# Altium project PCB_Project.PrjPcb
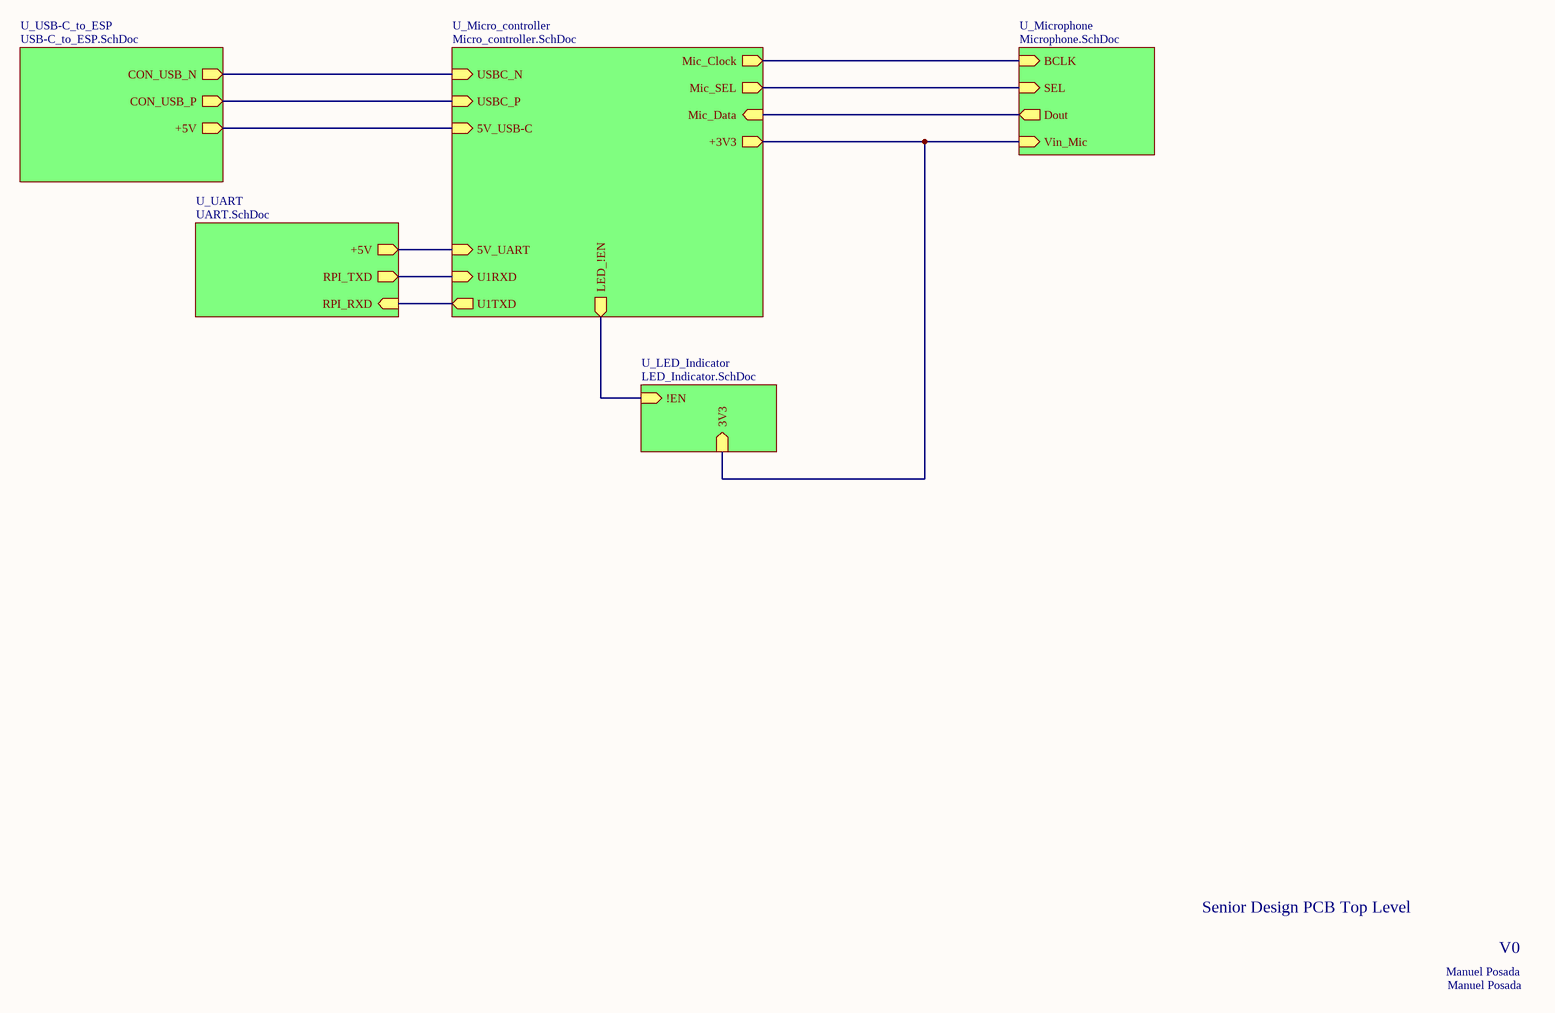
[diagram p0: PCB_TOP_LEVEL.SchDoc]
6 sheets, 63 parts. Net scope: hierarchical (ports join the sheet entries above them; power ports are global).
Board file: PCB1.PcbDoc
Sheets:
  PCB_TOP_LEVEL.SchDoc
    U_Micro_controller = Micro_controller.SchDoc
    U_USB-C_to_ESP = USB-C_to_ESP.SchDoc
    U_Microphone = Microphone.SchDoc
    U_UART = UART.SchDoc
    U_LED_Indicator = LED_Indicator.SchDoc

## Sheet PCB_TOP_LEVEL.SchDoc
size B; SheetNumber: 1; SheetTotal: 6

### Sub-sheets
U_LED_Indicator = LED_Indicator.SchDoc: 3V3 (in), !EN (in)
U_Micro_controller = Micro_controller.SchDoc: Mic_Data (in), Mic_SEL (out), Mic_Clock (out), U1TXD (out), U1RXD (in), LED_!EN (out), USBC_N (in), USBC_P (in), 5V_USB-C (in), 5V_UART (in), +3V3 (out)
U_Microphone = Microphone.SchDoc: Vin_Mic (in), BCLK (in), Dout (out), SEL (in)
U_UART = UART.SchDoc: RPI_RXD (in), RPI_TXD (out), +5V (out)
U_USB-C_to_ESP = USB-C_to_ESP.SchDoc: +5V (out), CON_USB_N (out), CON_USB_P (out)

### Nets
3.3V: sheet U_Micro_controller/+3V3, sheet U_Microphone/Vin_Mic, sheet U_LED_Indicator/3V3
GPIO6: sheet U_Micro_controller/Mic_SEL, sheet U_Microphone/SEL
GPIO7: sheet U_Micro_controller/Mic_Data, sheet U_Microphone/Dout
GPIO8: sheet U_Micro_controller/Mic_Clock, sheet U_Microphone/BCLK
GPIO17: sheet U_Micro_controller/U1TXD, sheet U_UART/RPI_RXD
GPIO18: sheet U_Micro_controller/U1RXD, sheet U_UART/RPI_TXD
GPIO19: sheet U_Micro_controller/USBC_N, sheet U_USB-C_to_ESP/CON_USB_N
GPIO20: sheet U_Micro_controller/USBC_P, sheet U_USB-C_to_ESP/CON_USB_P
GPIO38: sheet U_Micro_controller/LED_!EN, sheet U_LED_Indicator/!EN
NetR1_1: sheet U_Micro_controller/5V_USB-C, sheet U_USB-C_to_ESP/+5V
NetR4_1: sheet U_Micro_controller/5V_UART, sheet U_UART/+5V

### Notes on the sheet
- Senior Design PCB Top Level
- Manuel Posada
- V0

## Sheet Micro_controller.SchDoc
size C; SheetNumber: 3; SheetTotal: 6
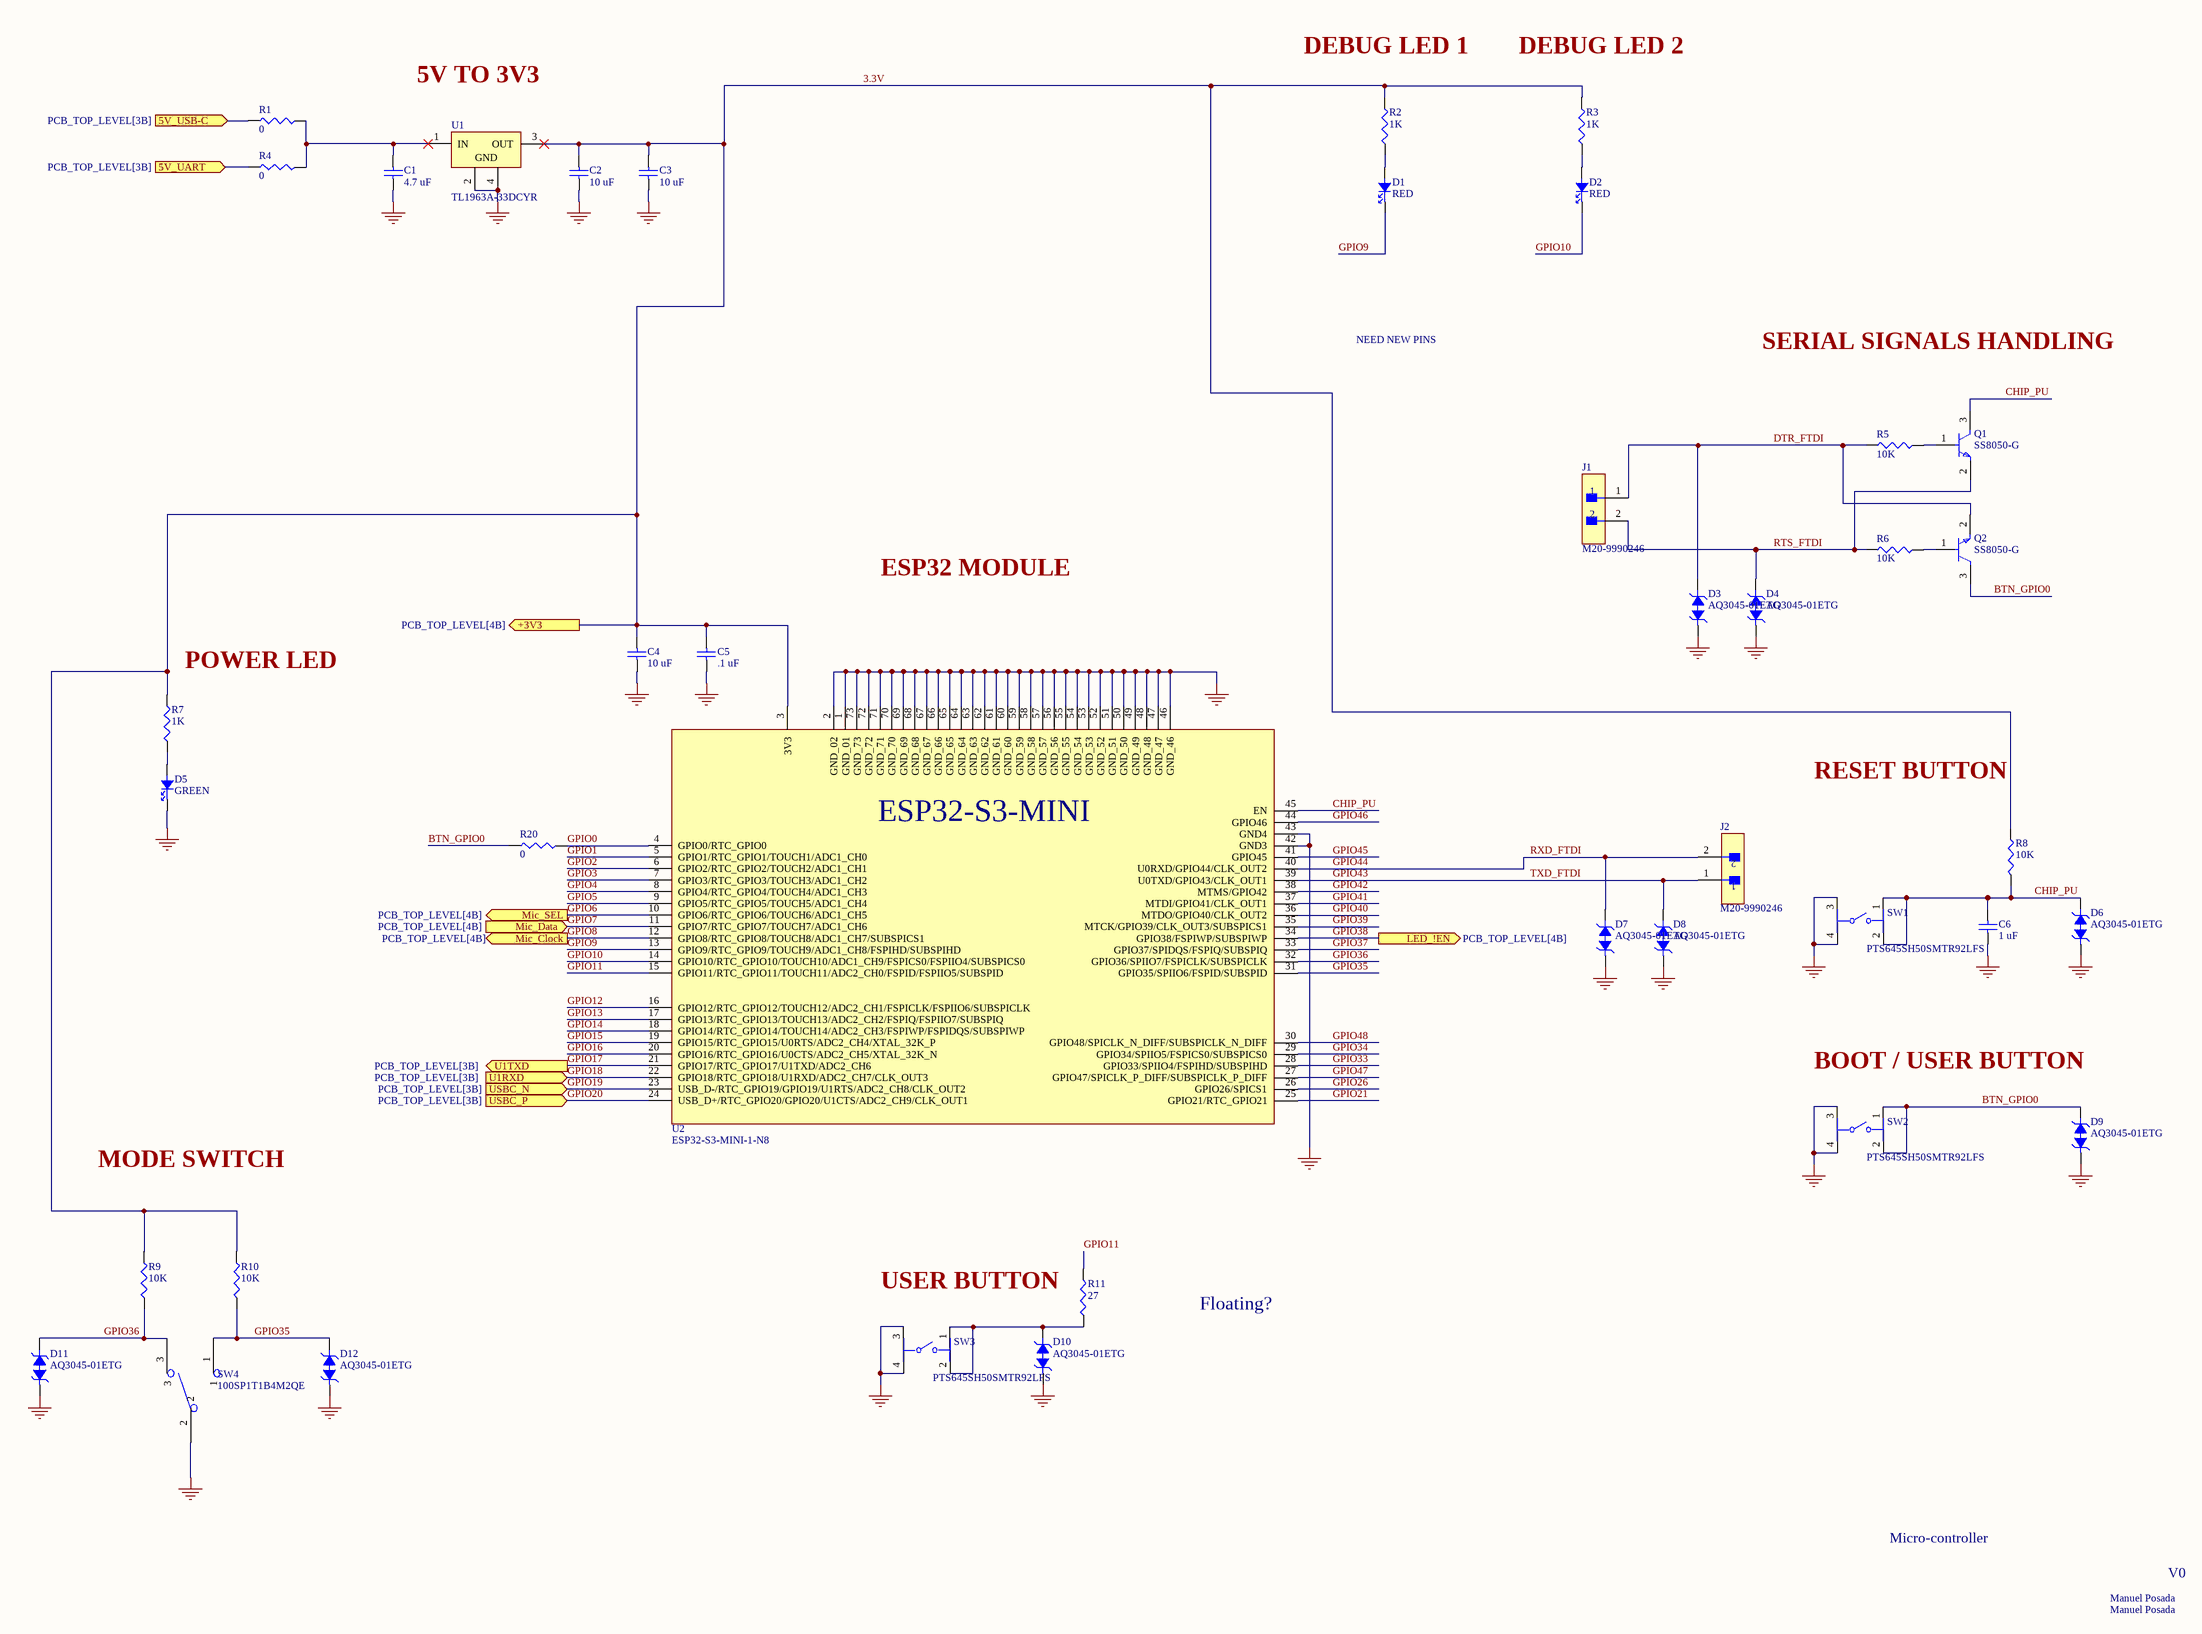
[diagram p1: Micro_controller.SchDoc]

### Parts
C1  4.7 uF  [CAP_CL21_SAM-L]
C2  10 uF  [CAP_CL21_SAM-L]
C3  10 uF  [CAP_CL21_SAM-L]
C4  10 uF  [CAP_CL21_SAM-L]
C5  .1 uF  [CAP_CL21_SAM-L]
C6  1 uF  [CAP_CL21_SAM-L]
D1  RED  [LED0402R]
D2  RED  [LED0402R]
D3  AQ3045-01ETG  [SOD882]
D4  AQ3045-01ETG  [SOD882]
D5  GREEN  [LED0402G]
D6  AQ3045-01ETG  [SOD882]
D7  AQ3045-01ETG  [SOD882]
D8  AQ3045-01ETG  [SOD882]
D9  AQ3045-01ETG  [SOD882]
D10  AQ3045-01ETG  [SOD882]
D11  AQ3045-01ETG  [SOD882]
D12  AQ3045-01ETG  [SOD882]
J1  M20-9990246  [CONN2_M20-999_1x2_HRW]
J2  M20-9990246  [CONN2_M20-999_1x2_HRW]
Q1  SS8050-G  [FP-SS8050-G-IPC_B]
Q2  SS8050-G  [FP-SS8050-G-IPC_B]
R1  0  [RES_1220_SUS-L]
R2  1K  [RES_1220_SUS-L]
R3  1K  [RES_1220_SUS-L]
R4  0  [RES_1220_SUS-L]
R5  10K  [RES_1220_SUS-L]
R6  10K  [RES_1220_SUS-L]
R7  1K  [RES_1220_SUS-L]
R8  10K  [RES_1220_SUS-L]
R9  10K  [RES_1220_SUS-L]
R10  10K  [RES_1220_SUS-L]
R11  27  [RES_1220_SUS-L]
R20  0  [RES_1220_SUS-L]
SW1  PTS645SH50SMTR92LFS  [FP-PTS645SH50SMTR92LFS-MFG]
SW2  PTS645SH50SMTR92LFS  [FP-PTS645SH50SMTR92LFS-MFG]
SW3  PTS645SH50SMTR92LFS  [FP-PTS645SH50SMTR92LFS-MFG]
SW4  100SP1T1B4M2QE  [100SP1T1_EWI]
U1  TL1963A-33DCYR  [DCY0004A_N]
U2  ESP32-S3-MINI-1-N8  [XCVR_ESP32-S3-MINI-1-N8]

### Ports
5V_UART (in, see PCB_TOP_LEVEL[3B]), 5V_USB-C (in, see PCB_TOP_LEVEL[3B]), +3V3 (out, see PCB_TOP_LEVEL[4B]), LED_!EN (out, see PCB_TOP_LEVEL[4B]), Mic_Clock (out, see PCB_TOP_LEVEL[4B]), Mic_Data (in, see PCB_TOP_LEVEL[4B]), Mic_SEL (out, see PCB_TOP_LEVEL[4B]), U1RXD (in, see PCB_TOP_LEVEL[3B]), U1TXD (out, see PCB_TOP_LEVEL[3B]), USBC_N (in, see PCB_TOP_LEVEL[3B]), USBC_P (in, see PCB_TOP_LEVEL[3B])

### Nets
GND: C1.1 C2.1 C3.1 C4.1 C5.1 C6.1 D3.1 D4.1 D5.1 D6.1 D7.1 D8.1 D9.1 D10.1 D11.1 D12.1 SW1.3 SW1.4 SW2.3 SW2.4 SW3.3 SW3.4 SW4.2 U1.2(GND) U1.4(GND) U2.1(GND_01) U2.2(GND_02) U2.42(GND3) U2.43(GND4) U2.46(GND_46) U2.47(GND_47) U2.48(GND_48) U2.49(GND_49) U2.50(GND_50) U2.51(GND_51) U2.52(GND_52) U2.53(GND_53) U2.54(GND_54) U2.55(GND_55) U2.56(GND_56) U2.57(GND_57) U2.58(GND_58) U2.59(GND_59) U2.60(GND_60) U2.61(GND_61) U2.62(GND_62) U2.63(GND_63) U2.64(GND_64) U2.65(GND_65) U2.66(GND_66) U2.67(GND_67) U2.68(GND_68) U2.69(GND_69) U2.70(GND_70) U2.71(GND_71) U2.72(GND_72) U2.73(GND_73)
3.3V: C2.2 C3.2 C4.2 C5.2 R2.2 R3.2 R7.2 R8.2 R9.2 R10.2 U1.3(OUT) U2.3(3V3) ; port +3V3
BTN_GPIO0: D9.2 Q2.3(C) R20.1 SW2.1 SW2.2
CHIP_PU: C6.2 D6.2 Q1.3(C) R8.1 SW1.1 SW1.2 U2.45(EN)
DTR_FTDI: D3.2 J1.1 Q2.2(E) R5.1
GPIO0: R20.2 U2.4(GPIO0/RTC_GPIO0)
GPIO1: U2.5(GPIO1/RTC_GPIO1/TOUCH1/ADC1_CH0)
GPIO2: U2.6(GPIO2/RTC_GPIO2/TOUCH2/ADC1_CH1)
GPIO3: U2.7(GPIO3/RTC_GPIO3/TOUCH3/ADC1_CH2)
GPIO4: U2.8(GPIO4/RTC_GPIO4/TOUCH4/ADC1_CH3)
GPIO5: U2.9(GPIO5/RTC_GPIO5/TOUCH5/ADC1_CH4)
GPIO6: U2.10(GPIO6/RTC_GPIO6/TOUCH6/ADC1_CH5) ; port Mic_SEL
GPIO7: U2.11(GPIO7/RTC_GPIO7/TOUCH7/ADC1_CH6) ; port Mic_Data
GPIO8: U2.12(GPIO8/RTC_GPIO8/TOUCH8/ADC1_CH7/SUBSPICS1) ; port Mic_Clock
GPIO9: D1.1 U2.13(GPIO9/RTC_GPIO9/TOUCH9/ADC1_CH8/FSPIHD/SUBSPIHD)
GPIO10: D2.1 U2.14(GPIO10/RTC_GPIO10/TOUCH10/ADC1_CH9/FSPICS0/FSPIIO4/SUBSPICS0)
GPIO11: R11.2 U2.15(GPIO11/RTC_GPIO11/TOUCH11/ADC2_CH0/FSPID/FSPIIO5/SUBSPID)
GPIO12: U2.16(GPIO12/RTC_GPIO12/TOUCH12/ADC2_CH1/FSPICLK/FSPIIO6/SUBSPICLK)
GPIO13: U2.17(GPIO13/RTC_GPIO13/TOUCH13/ADC2_CH2/FSPIQ/FSPIIO7/SUBSPIQ)
GPIO14: U2.18(GPIO14/RTC_GPIO14/TOUCH14/ADC2_CH3/FSPIWP/FSPIDQS/SUBSPIWP)
GPIO15: U2.19(GPIO15/RTC_GPIO15/U0RTS/ADC2_CH4/XTAL_32K_P)
GPIO16: U2.20(GPIO16/RTC_GPIO16/U0CTS/ADC2_CH5/XTAL_32K_N)
GPIO17: U2.21(GPIO17/RTC_GPIO17/U1TXD/ADC2_CH6) ; port U1TXD
GPIO18: U2.22(GPIO18/RTC_GPIO18/U1RXD/ADC2_CH7/CLK_OUT3) ; port U1RXD
GPIO19: U2.23(USB_D-/RTC_GPIO19/GPIO19/U1RTS/ADC2_CH8/CLK_OUT2) ; port USBC_N
GPIO20: U2.24(USB_D+/RTC_GPIO20/GPIO20/U1CTS/ADC2_CH9/CLK_OUT1) ; port USBC_P
GPIO21: U2.25(GPIO21/RTC_GPIO21)
GPIO26: U2.26(GPIO26/SPICS1)
GPIO33: U2.28(GPIO33/SPIIO4/FSPIHD/SUBSPIHD)
GPIO34: U2.29(GPIO34/SPIIO5/FSPICS0/SUBSPICS0)
GPIO35: D12.2 R10.1 SW4.1 U2.31(GPIO35/SPIIO6/FSPID/SUBSPID)
GPIO36: D11.2 R9.1 SW4.3 U2.32(GPIO36/SPIIO7/FSPICLK/SUBSPICLK)
GPIO37: U2.33(GPIO37/SPIDQS/FSPIQ/SUBSPIQ)
GPIO38: U2.34(GPIO38/FSPIWP/SUBSPIWP) ; port LED_!EN
GPIO39: U2.35(MTCK/GPIO39/CLK_OUT3/SUBSPICS1)
GPIO40: U2.36(MTDO/GPIO40/CLK_OUT2)
GPIO41: U2.37(MTDI/GPIO41/CLK_OUT1)
GPIO42: U2.38(MTMS/GPIO42)
GPIO43: D8.2 J2.1 U2.39(U0TXD/GPIO43/CLK_OUT1)  [also labelled TXD_FTDI]
GPIO44: D7.2 J2.2 U2.40(U0RXD/GPIO44/CLK_OUT2)  [also labelled RXD_FTDI]
GPIO45: U2.41(GPIO45)
GPIO46: U2.44(GPIO46)
GPIO47: U2.27(GPIO47/SPICLK_P_DIFF/SUBSPICLK_P_DIFF)
GPIO48: U2.30(GPIO48/SPICLK_N_DIFF/SUBSPICLK_N_DIFF)
RTS_FTDI: D4.2 J1.2 Q1.2(E) R6.1
NetC1_2: C1.2 R1.2 R4.2 U1.1(IN)
NetD1_2: D1.2 R2.1
NetD2_2: D2.2 R3.1
NetD5_2: D5.2 R7.1
NetD10_2: D10.2 R11.1 SW3.1 SW3.2
NetQ1_1: Q1.1(B) R5.2
NetQ2_1: Q2.1(B) R6.2
NetR1_1: R1.1 ; port 5V_USB-C
NetR4_1: R4.1 ; port 5V_UART

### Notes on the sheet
- DEBUG LED 1
- DEBUG LED 2
- 5V TO 3V3
- SERIAL SIGNALS HANDLING
- NEED NEW PINS
- ESP32 MODULE
- (near R7) POWER LED
- RESET BUTTON
- BOOT / USER BUTTON
- MODE SWITCH
- USER BUTTON
- Floating?
- Micro-controller
- Manuel Posada
- V0

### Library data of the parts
C1 = CL21A475KAQNNNE: 25V 4.7uF X5R ±10% 0805 Multilayer Ceramic Capacitors MLCC - SMD/SMT ROHS; Manufacturer: Samsung Electro-Mechanics; Value: 4.7µF
C2-C4 = CL21B106KOQNNNE: 16V 10uF X7R ±10% 0805 Multilayer Ceramic Capacitors MLCC - SMD/SMT ROHS; Manufacturer: Samsung Electro-Mechanics; Value: 10µF
C5 = CL21B104KBCNNNC: 50V 100nF X7R ±10% 0805 Multilayer Ceramic Capacitors MLCC - SMD/SMT ROHS; Manufacturer: Samsung Electro-Mechanics
C6 = CL21B105KBFNNNE: 50V 1uF X7R ±10% 0805 Multilayer Ceramic Capacitors MLCC - SMD/SMT ROHS; Manufacturer: Samsung Electro-Mechanics; Value: 1µF
D1 D2 = VLMS1500-GS08: LED RED 0402 SMD; Manufacturer: Vishay; Shape: Rectangular; Forward Current: 30mA; Forward Voltage: 2.4V; Luminous Intensity-Nom: 54mcd; Channels: 1; Optoelectronic Device Type: SINGLE COLOR LED; Reverse Voltage-Max: 5V; Viewing Angle: 130°; Overall Height: 0.35mm
D3 D4 D6-D12 = AQ3045-01ETG: TVS DIODE 5.3VWM 12VC SOD882; Manufacturer: Littelfuse; Diode Element Material: SILICON; Package Body Material: Plastic; Polarity: Bidirectional; Max Breakdown Voltage: 9V; Min Breakdown Voltage: 6.8V; Diode Type: TRANS VOLTAGE SUPPRESSOR; Non-rep Peak Rev Power Dis-Max: 40W; Number of Elements: 1; Rep Pk Reverse Voltage-Max: 5.3V; Reference Standard: AEC-Q101
D5 = VLMG1500-GS08: LED YLW-GRN 0402 SMD; Manufacturer: Vishay; Color: Green,Yellow; Lens Color: Clear; Viewing Angle: 130°; Forward Current: 30mA; Forward Voltage: 2V; Luminous Intensity: 35mcd; Dominant Wavelength: 571nm; Test Current: 20mA; Number of Elements: 1; Power Dissipation: 75mW; Lens Style: Rectangular; Reverse Voltage: 5V
J1 J2 = M20-9990246: Connector Header Through Hole 2 position 0.100" (2.54mm); Manufacturer: Harwin; Connector Type: Male Pin; Contact Resistance: 30mΩ; Current Rating: 3A; Dielectric Material: Polyamide; Gender: Male; Insulation Resistance: 1GΩ; Number of Contacts: 2; Voltage Rating (AC): 750V
Q1 Q2 = SS8050-G: TRANS NPN 25V 1.5A SOT23-3; Manufacturer: Comchip
R1 R4 R20 = RC0805JR-070RL: GENERAL PURPOSE CHIP RESISTOR Metal Glaze/thick Film, 0.125W, 0ohm, Surface Mount, 0805; Manufacturer: Yageo Group; Power Dissipation: 125mW; Value: 0Ω; Temperature Coefficient: 300ppm/°C; Tolerance: 5%; Voltage Rating: 150V
R2 R3 R7 = RG2012P-102-B-T5: Res Thin Film 0805 1K Ohm 0.1% 0.125W(1/8W) ±25ppm/C Sulfur Resistant Pad SMD Automotive T/R; Manufacturer: Susumu; Max Power Dissipation: 125mW; Value: 1kΩ; Temperature Coefficient: 25ppm/°C; Voltage Rating: 150V
R5 R6 R8-R10 = RG2012P-103-B-T5: Res Thin Film 0805 10K Ohm 0.1% 0.125W(1/8W) ±25ppm/C Sulfur Resistant Pad SMD Automotive T/R; Manufacturer: Susumu; Power Dissipation: 125mW; Value: 10kΩ; Temperature Coefficient: 25ppm/°C; Voltage Rating: 150V
R11 = RG2012Q-270-D-T5: Fixed Resistor, Thin Film, 0.125W, 27ohm, 150V, 0.5% +/-Tol, 50ppm/Cel, Surface Mount, 0805; Manufacturer: Susumu; Power Dissipation: 125mW; Value: 27Ω; Temperature Coefficient: 50ppm/°C
SW1-SW3 = PTS645SH50SMTR92LFS: SWITCH TACTILE SPST-NO 0.05A 12V; Manufacturer: ITT C&K; Manufacturer Series: PTS645; Actuator Type: Pushbutton; Contact Current(DC)-Max: 50mA; Contact DC Max Rating R Load: 0.05A@12VDC; Contact Resistance: 0.1mR; Dielectric Withstand Volts: 250VACV; Electrical Life: 100000Cycles; Insulation Resistance: 100GR; PCB Hole Count: 4; Switch Action: MOMENTARY; Switch Function: SPST; Switch Type: Keypad; Body Breadth: 5.9944inch; Body Height: 3.4544mm; Body Length or Diameter: 5.9944mm
SW4 = 100SP1T1B4M2QE: Switch Toggle ON None ON SPDT Round Lever PC Pins 5A 250VAC 28VDC PC Mount; Manufacturer: E-Switch; Actuator Length: 10.414mm; Actuator Material: Brass, Chrome; Contact Voltage Rating (AC): 120V; Electrical Life: 50kcycles; Illumination Type: Illuminated, Non-Illuminated; Max Voltage Rating (DC): 28V; Number of Positions: 2; Sealable: EPOXY TERMINAL SEALED; Switch Function: On-On
U1 = TL1963A-33DCYR: IC REG LINEAR 3.3V 1.5A SOT223-4; Manufacturer: Texas Instruments; Package Body Material: Plastic; Adjustability: FIXED; Dropout Voltage1-Max: 550mV; Dropout Voltage1-Nom: 340mV; Input Voltage Absolute-Max: 20V; Min Input Voltage: 3.8V; Line Regulation-Max: 0.01%; Load Regulation-Max: 0.07%; Channels: 1; Output Voltage1-Max: 3.4V; Output Voltage1-Min: 3.2V; Regulator Type: FIXED POSITIVE SINGLE OUTPUT LDO REGULATOR; Voltage Tolerance-Max: 3%; Qualification Status: Not Qualified
U2 = ESP32-S3-MINI-1-N8: SMD Module, ESP32-S3FN8, 8 mb Sp; Manufacturer: Espressif Systems

## Sheet USB-C_to_ESP.SchDoc
size B; SheetNumber: 2; SheetTotal: 6
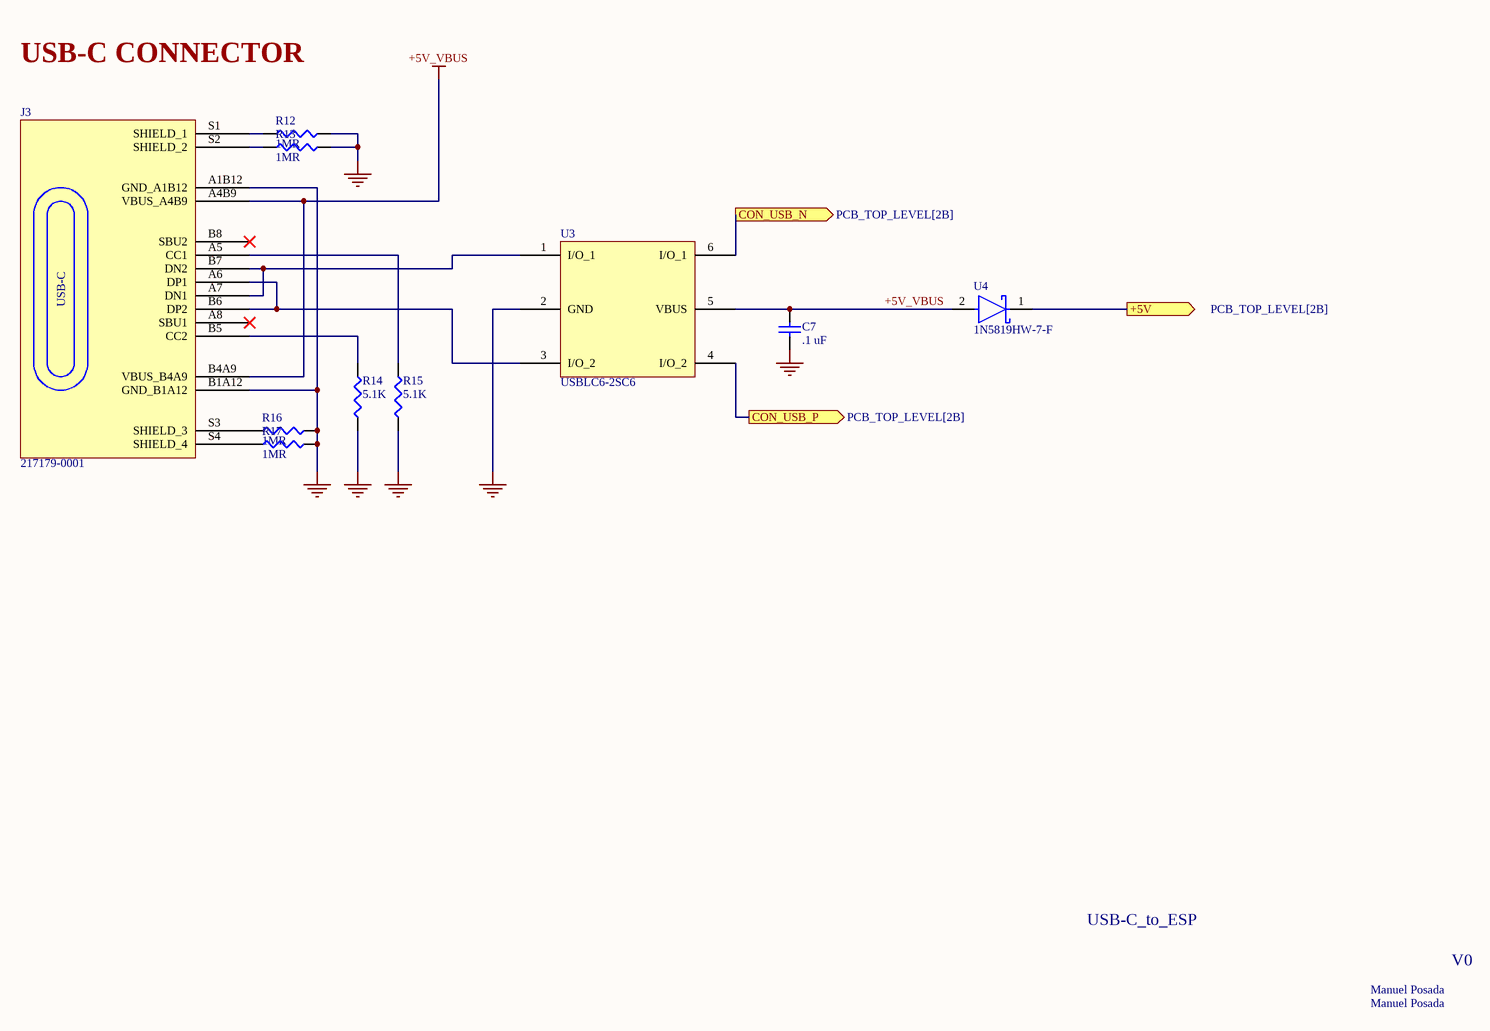
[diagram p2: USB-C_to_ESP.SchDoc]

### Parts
C7  .1 uF  [CAP_CL21_SAM-L]
J3  217179-0001  [FP-2171790001-MFG]
R12  1MR  [RES_1220_SUS-L]
R13  1MR  [RES_1220_SUS-L]
R14  5.1K  [RES_1220_SUS-L]
R15  5.1K  [RES_1220_SUS-L]
R16  1MR  [RES_1220_SUS-L]
R17  1MR  [RES_1220_SUS-L]
U3  USBLC6-2SC6  [SOT23-6L_STM]
U4  1N5819HW-7-F  [FP-SOD123-IPC_B]

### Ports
+5V (out, see PCB_TOP_LEVEL[2B]), CON_USB_N (out, see PCB_TOP_LEVEL[2B]), CON_USB_P (out, see PCB_TOP_LEVEL[2B])

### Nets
+5V_VBUS: C7.2 J3.A4B9(VBUS_A4B9) J3.B4A9(VBUS_B4A9) U3.5(VBUS) U4.2(A)
GND: C7.1 J3.A1B12(GND_A1B12) J3.B1A12(GND_B1A12) R12.2 R13.2 R14.1 R15.1 R16.2 R17.2 U3.2(GND)
GPIO19: U3.6(I/O_1) ; port CON_USB_N
GPIO20: U3.4(I/O_2) ; port CON_USB_P
NetJ3_A5: J3.A5(CC1) R15.2
NetJ3_A6: J3.A6(DP1) J3.B6(DP2) U3.3(I/O_2)
NetJ3_A7: J3.A7(DN1) J3.B7(DN2) U3.1(I/O_1)
NetJ3_B5: J3.B5(CC2) R14.2
NetJ3_S1: J3.S1(SHIELD_1) R12.1
NetJ3_S2: J3.S2(SHIELD_2) R13.1
NetJ3_S3: J3.S3(SHIELD_3) R16.1
NetJ3_S4: J3.S4(SHIELD_4) R17.1
NetR1_1: U4.1(C) ; port +5V

Not connected (* = marked no-connect by the designer): J3 A8(SBU1)* B8(SBU2)*

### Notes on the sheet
- USB-C CONNECTOR
- USB-C_to_ESP
- Manuel Posada
- V0

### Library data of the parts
C7 = CL21B104KBCNNNC: as C5 on sheet Micro_controller
J3 = 217179-0001: CONN RCP USB2.0 TYP C 24P SMD RA; Manufacturer: Molex
R12 R13 R16 R17 = RG2012P-105-B-T5: Res Thin Film 0805 1M Ohm 0.1% 0.125W(1/8W) ±25ppm/C Sulfur Resistant Pad SMD Automotive T/R; Manufacturer: Susumu; Power Dissipation: 125mW; Value: 1MΩ; Temperature Coefficient: 25ppm/°C; Voltage Rating: 150V
R14 R15 = RG2012P-512-B-T5: Res Thin Film 0805 5.1K Ohm 0.1% 0.125W(1/8W) ±25ppm/C Sulfur Resistant Pad SMD Automotive T/R; Manufacturer: Susumu; Max Power Dissipation: 125mW; Value: 5.1kΩ; Temperature Coefficient: 25ppm/°C; Voltage Rating: 150V
U3 = USBLC6-2SC6: 17V Clamp 5A (8/20µs) Ipp Tvs Diode Surface Mount SOT-23-6; Manufacturer: STMicroelectronics; Breakdown Voltage: 6V; Value: 2.5pF; Data Rate: 480Mbps; Direction: Unidirectional; Element Configuration: Dual; ESD Protection: Yes; Forward Voltage: 1.1V; Leakage Current: 150nA; Max Junction Temperature (Tj): 125°C; Max Repetitive Reverse Voltage (Vrrm): 5.25V; Number of Bidirectional Channels: 2; Number of Elements: 1; Reverse Standoff Voltage: 5V; Test Current: 1mA
U4 = 1N5819HW-7-F: DIODE SCHOTTKY 40V 1A SOD123; Manufacturer: Diodes Inc.; Value: 50pF; Element Configuration: Single; Forward Voltage: 750mV; Max Forward Surge Current (Ifsm): 25A; Max Junction Temperature (Tj): 125°C; Max Power Dissipation: 450mW; Number of Elements: 1; Peak Reverse Current: 1mA; Polarity: Standard

## Sheet Microphone.SchDoc
size A; SheetNumber: 6; SheetTotal: 6
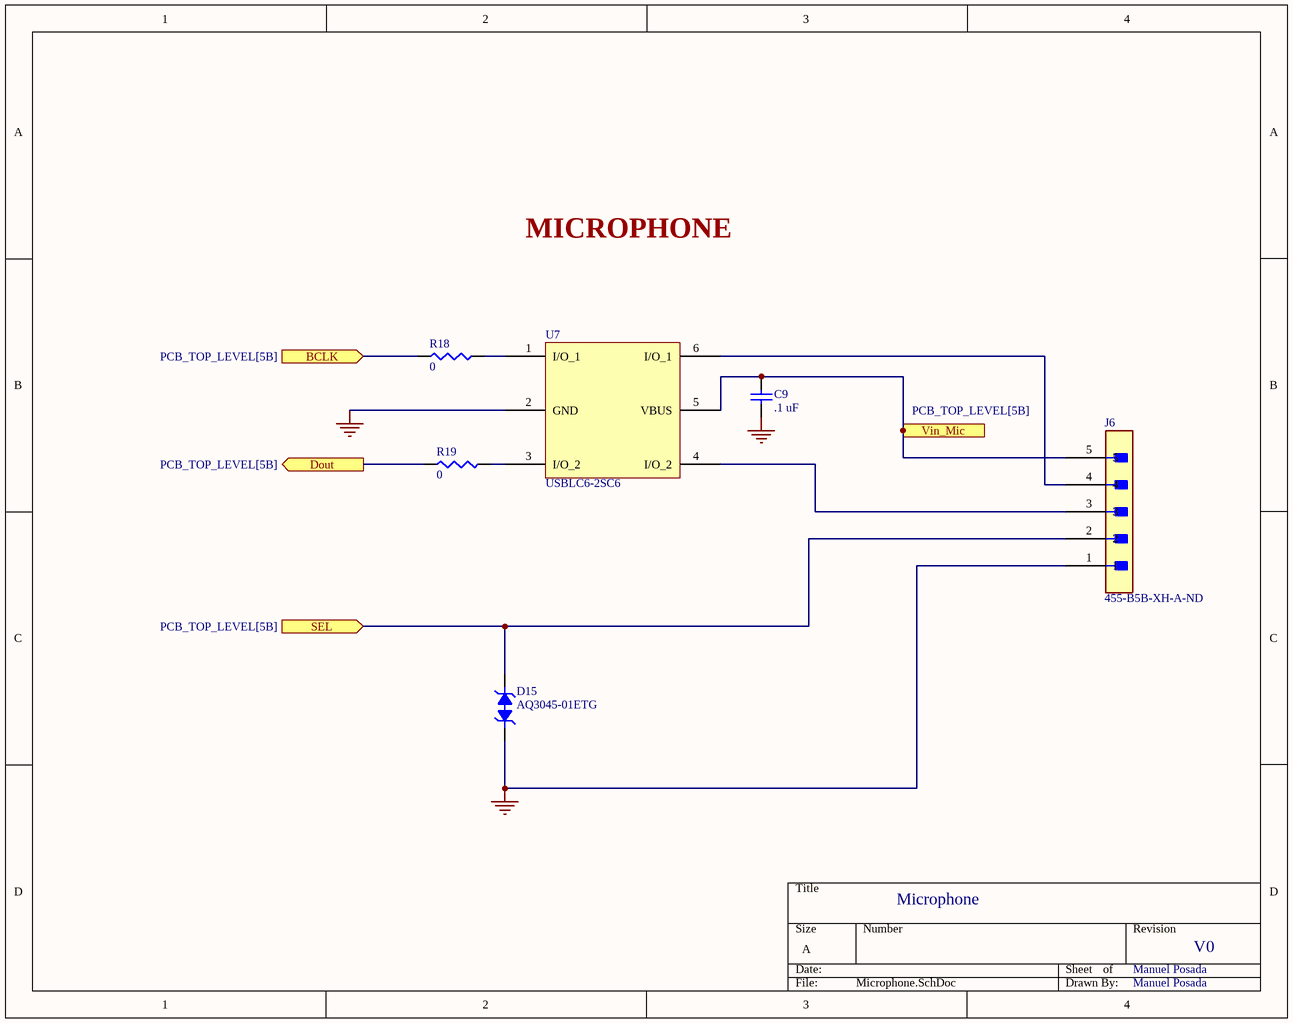
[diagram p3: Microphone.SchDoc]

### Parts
C9  .1 uF  [CAP_CL21_SAM-L]
D15  AQ3045-01ETG  [SOD882]
J6  455-B5B-XH-A-ND  [CONN_B5B-XH-A_JST]
R18  0  [RES_1220_SUS-L]
R19  0  [RES_1220_SUS-L]
U7  USBLC6-2SC6  [SOT23-6L_STM]

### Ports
BCLK (in, see PCB_TOP_LEVEL[5B]), Dout (out, see PCB_TOP_LEVEL[5B]), SEL (in, see PCB_TOP_LEVEL[5B]), Vin_Mic (in, see PCB_TOP_LEVEL[5B])

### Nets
GND: C9.1 D15.1 J6.1 U7.2(GND)
3.3V: C9.2 J6.5 U7.5(VBUS) ; port Vin_Mic
GPIO6: D15.2 J6.2 ; port SEL
GPIO7: R19.1 ; port Dout
GPIO8: R18.1 ; port BCLK
NetJ6_3: J6.3 U7.4(I/O_2)
NetJ6_4: J6.4 U7.6(I/O_1)
NetR18_2: R18.2 U7.1(I/O_1)
NetR19_2: R19.2 U7.3(I/O_2)

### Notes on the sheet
- MICROPHONE
- Microphone
- Manuel Posada
- V0

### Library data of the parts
C9 = CL21B104KBCNNNC: as C5 on sheet Micro_controller
D15 = AQ3045-01ETG: as D3 on sheet Micro_controller
J6 = B5B-XH-A: Board Connector, 5 Contact(s), 1 Row(s), Male, Straight, 0.098 inch Pitch, Solder Terminal; Manufacturer: JST; Contact Resistance: 20mΩ; Current Rating: 3A; Insulation Resistance: 1GΩ
R18 R19 = RC0805JR-070RL: as R1 on sheet Micro_controller
U7 = USBLC6-2SC6: as U3 on sheet USB-C_to_ESP

## Sheet UART.SchDoc
size A; SheetNumber: 4; SheetTotal: 6
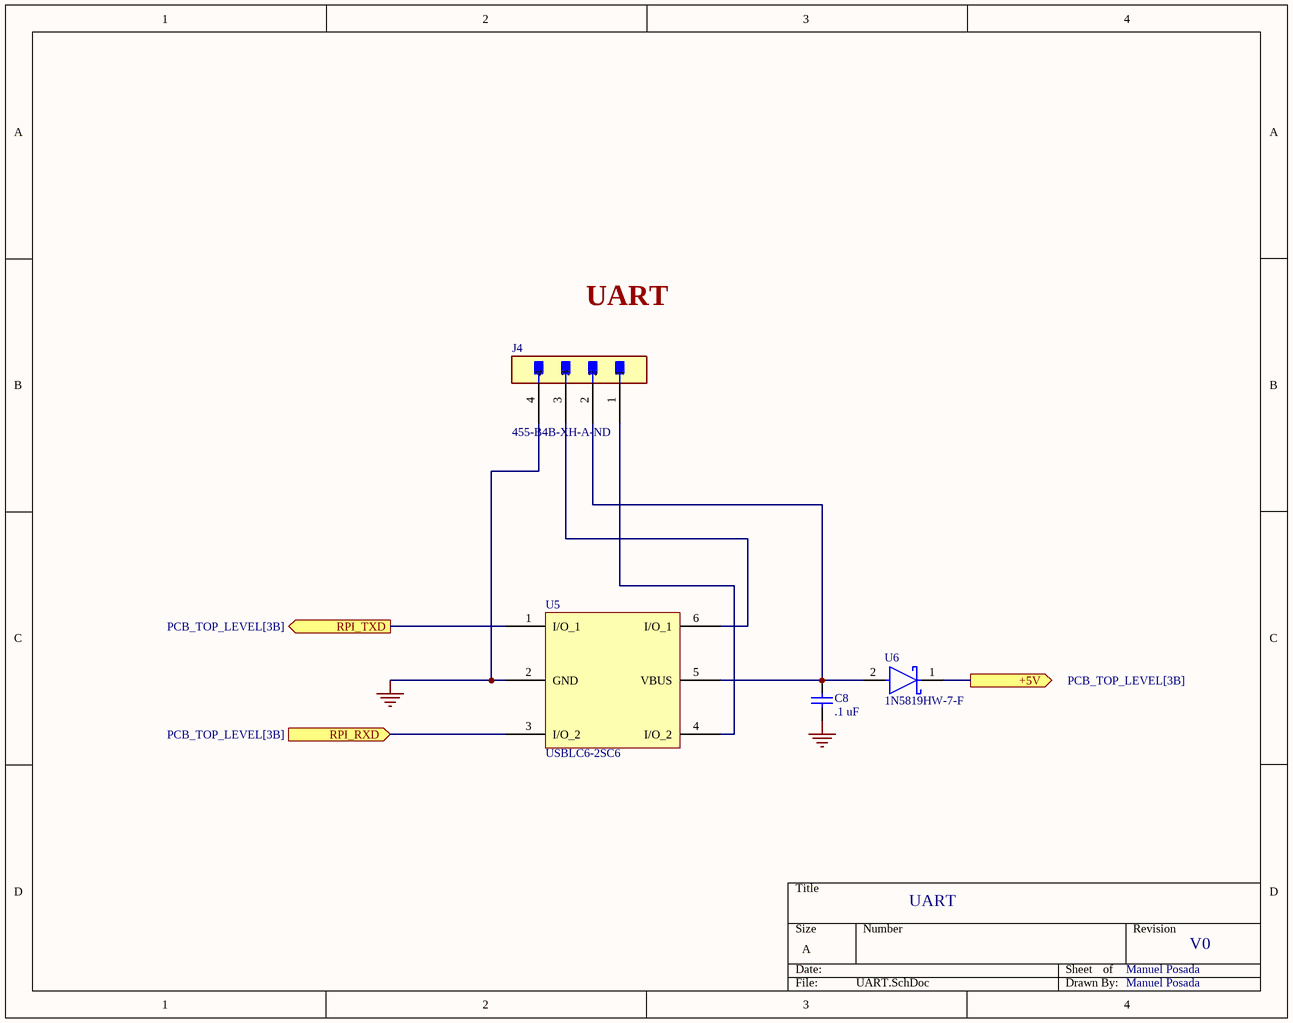
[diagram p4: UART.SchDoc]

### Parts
C8  .1 uF  [CAP_CL21_SAM-L]
J4  455-B4B-XH-A-ND  [CONN_B4B-XH-A_JST]
U5  USBLC6-2SC6  [SOT23-6L_STM]
U6  1N5819HW-7-F  [FP-SOD123-IPC_B]

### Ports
+5V (out, see PCB_TOP_LEVEL[3B]), RPI_RXD (in, see PCB_TOP_LEVEL[3B]), RPI_TXD (out, see PCB_TOP_LEVEL[3B])

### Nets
GND: C8.1 J4.4 U5.2(GND)
GPIO17: U5.3(I/O_2) ; port RPI_RXD
GPIO18: U5.1(I/O_1) ; port RPI_TXD
NetC8_2: C8.2 J4.2 U5.5(VBUS) U6.2(A)
NetJ4_1: J4.1 U5.4(I/O_2)
NetJ4_3: J4.3 U5.6(I/O_1)
NetR4_1: U6.1(C) ; port +5V

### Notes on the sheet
- UART
- Manuel Posada
- V0

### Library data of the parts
C8 = CL21B104KBCNNNC: as C5 on sheet Micro_controller
J4 = B4B-XH-A: Board Connector, 4 Contact(s), 1 Row(s), Male, Straight, Solder Terminal; Manufacturer: JST; Contact Resistance: 20mΩ; Current Rating: 3A; Insulation Resistance: 1GΩ
U5 = USBLC6-2SC6: as U3 on sheet USB-C_to_ESP
U6 = 1N5819HW-7-F: as U4 on sheet USB-C_to_ESP

## Sheet LED_Indicator.SchDoc
size A; SheetNumber: 5; SheetTotal: 6
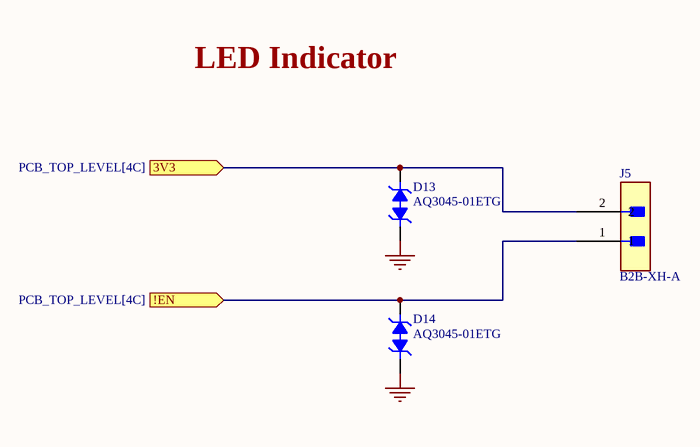
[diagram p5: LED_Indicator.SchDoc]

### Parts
D13  AQ3045-01ETG  [SOD882]
D14  AQ3045-01ETG  [SOD882]
J5  B2B-XH-A  [CONN_B2B-XH-A_JST]

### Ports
3V3 (in, see PCB_TOP_LEVEL[4C]), !EN (in, see PCB_TOP_LEVEL[4C])

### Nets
GND: D13.1 D14.1
3.3V: D13.2 J5.2 ; port 3V3
GPIO38: D14.2 J5.1 ; port !EN

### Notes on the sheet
- LED Indicator

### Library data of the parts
D13 D14 = AQ3045-01ETG: as D3 on sheet Micro_controller
J5 = B2B-XH-A: Board Connector, 2 Contact(s), 1 Row(s), Male, Straight, Solder Terminal; Manufacturer: JST; Contact Resistance: 20mΩ; Current Rating: 3A; Insulation Resistance: 1GΩ

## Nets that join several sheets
GND: Micro_controller (57 pins), USB-C_to_ESP (10 pins), Microphone (C9.1 D15.1 J6.1 U7.2), UART (C8.1 J4.4 U5.2), LED_Indicator (D13.1 D14.1)
3.3V: Micro_controller (12 pins), Microphone (C9.2 J6.5 U7.5), LED_Indicator (D13.2 J5.2)
GPIO6: Micro_controller (U2.10), Microphone (D15.2 J6.2)
GPIO7: Micro_controller (U2.11), Microphone (R19.1)
GPIO8: Micro_controller (U2.12), Microphone (R18.1)
GPIO17: Micro_controller (U2.21), UART (U5.3)
GPIO18: Micro_controller (U2.22), UART (U5.1)
GPIO19: Micro_controller (U2.23), USB-C_to_ESP (U3.6)
GPIO20: Micro_controller (U2.24), USB-C_to_ESP (U3.4)
GPIO38: Micro_controller (U2.34), LED_Indicator (D14.2 J5.1)
NetR1_1: Micro_controller (R1.1), USB-C_to_ESP (U4.1)
NetR4_1: Micro_controller (R4.1), UART (U6.1)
